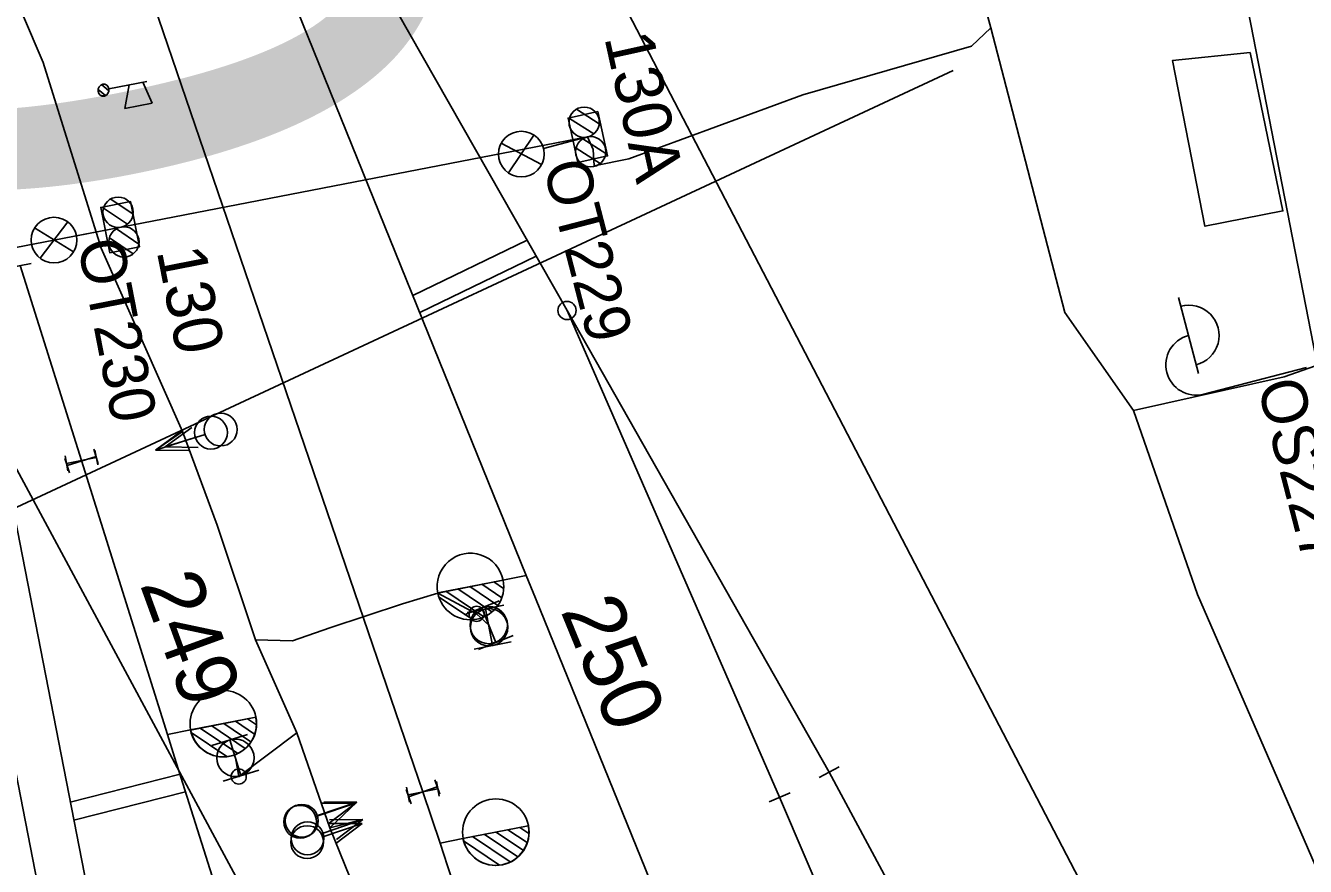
# Model space of a CAD drawing. Extents: x -545846 to -545044, y -1122650 to -1119108.
# Drawn here: x -545614.75 to -545572.52, y -1119663.02 to -1119635.26 of the extents above; entities that cross this region are included whole.
import ezdxf

# ---------------------------------------------------------------- set-up
doc = ezdxf.new("R2010")
doc.units = 0
for name, color, linetype in [('osvětlené plochy-hodnota-obrys', 7, 'Continuous'), ('Vrstva 1', 7, 'Continuous'), ('Vrstva 11 - Trakce', 7, 'Continuous'), ('Vrstva 12', 7, 'Continuous'), ('Vrstva 12 - Trakce zaklady', 7, 'Continuous'), ('Vrstva 2', 7, 'Continuous'), ('Vrstva 25', 7, 'Continuous'), ('Vrstva 26', 7, 'Continuous'), ('Vrstva 27', 7, 'Continuous'), ('Vrstva 28 - zabzar', 7, 'Continuous'), ('Vrstva 3', 7, 'Continuous'), ('Vrstva 3 - Lisy - Pocitaci body', 7, 'Continuous'), ('Vrstva 33', 7, 'Continuous'), ('Vrstva 35', 7, 'Continuous'), ('Vrstva 4 - Teren - stezky - prechody - plochy', 7, 'Continuous'), ('Vrstva 63', 7, 'Continuous'), ('Vrstva 7', 7, 'Continuous')]:
    doc.layers.add(name, color=color, linetype=linetype)

msp = doc.modelspace()

# ---------------------------------------------------------------- linework, layer by layer
at = {"layer": 'osvětlené plochy-hodnota-obrys'}
msp.add_line((-545562.16, -1119697.713), (-545631.883, -1119563.683), dxfattribs=at)
for points in [[(-545441.658, -1120319.908), (-545444.67, -1120302.28), (-545584.854, -1119581.025)], [(-545577.736, -1119667.874), (-545599.026, -1119679.685), (-545626.403, -1119628.801)]]:
    msp.add_lwpolyline(points, dxfattribs=at)
at = {"layer": 'Vrstva 1'}
for p, q in [((-545607.841, -1119629.659), (-545598.232, -1119653.414)), ((-545596.887, -1119644.663), (-545589.872, -1119660.732))]:
    msp.add_line(p, q, dxfattribs=at)
for points in [[(-545618.295, -1119613.58), (-545616.929, -1119617.292), (-545611.113, -1119632.817), (-545601.641, -1119660.552), (-545601.077, -1119662.243)], [(-545604.672, -1119630.951), (-545604.24, -1119631.719), (-545596.887, -1119644.663), (-545588.234, -1119659.903)], [(-545614.934, -1119643.182), (-545612.911, -1119649.615), (-545610.067, -1119658.662)], [(-545616.651, -1119643.635), (-545609.752, -1119678.959), (-545604.997, -1119703.439)], [(-545598.232, -1119653.414), (-545597.93, -1119654.159), (-545592.335, -1119667.955), (-545585.744, -1119684.209)], [(-545610.067, -1119658.662), (-545609.834, -1119659.409), (-545607.007, -1119668.348), (-545602.189, -1119683.602)], [(-545588.234, -1119659.903), (-545581.761, -1119671.962), (-545577.409, -1119681.094), (-545571.948, -1119694.17)], [(-545589.872, -1119660.732), (-545584.463, -1119673.383), (-545580.691, -1119682.438), (-545575.646, -1119695.886)], [(-545601.077, -1119662.243), (-545600.827, -1119662.999), (-545596.107, -1119677.118), (-545590.549, -1119693.752)]]:
    msp.add_lwpolyline(points, dxfattribs=at)
at = {"layer": 'Vrstva 11 - Trakce'}
for p, q in [((-545596.579, -1119638.02), (-545595.826, -1119638.5)), ((-545596.803, -1119638.322), (-545596.003, -1119638.832)), ((-545596.365, -1119638.999), (-545595.61, -1119639.48)), ((-545596.588, -1119639.302), (-545595.79, -1119639.81)), ((-545611.945, -1119640.986), (-545611.205, -1119641.483)), ((-545612.177, -1119641.282), (-545611.39, -1119641.811)), ((-545611.755, -1119641.969), (-545611.012, -1119642.469)), ((-545611.985, -1119642.267), (-545611.2, -1119642.794))]:
    msp.add_line(p, q, dxfattribs=at)
msp.add_lwpolyline([(-545596.214, -1119638.936), (-545611.603, -1119641.91), (-545639.182, -1119647.235)], dxfattribs=at)
for centre in [(-545596.322, -1119638.448), (-545596.106, -1119639.424), (-545611.699, -1119641.419), (-545611.507, -1119642.401)]:
    msp.add_circle(centre, 0.5, dxfattribs=at)
at = {"layer": 'Vrstva 12'}
msp.add_lwpolyline([(-545574.352, -1119636.15), (-545576.905, -1119636.409), (-545575.84, -1119641.883), (-545573.267, -1119641.376)], close=True, dxfattribs=at)
at = {"layer": 'Vrstva 12 - Trakce zaklady'}
for p, q in [((-545595.876, -1119638.097), (-545595.552, -1119639.561)), ((-545612.27, -1119641.262), (-545611.289, -1119641.07)), ((-545612.27, -1119641.262), (-545612.27, -1119641.262)), ((-545611.977, -1119642.757), (-545610.996, -1119642.565))]:
    msp.add_line(p, q, dxfattribs=at)
for points in [[(-545596.528, -1119639.777), (-545596.852, -1119638.313), (-545595.876, -1119638.097), (-545595.552, -1119639.561), (-545596.528, -1119639.777)], [(-545596.852, -1119638.313), (-545595.876, -1119638.097), (-545595.876, -1119638.097)], [(-545596.852, -1119638.313), (-545596.852, -1119638.313), (-545596.528, -1119639.777), (-545596.528, -1119639.777)], [(-545596.528, -1119639.777), (-545595.552, -1119639.561), (-545595.552, -1119639.561)], [(-545611.289, -1119641.07), (-545610.996, -1119642.565), (-545611.977, -1119642.757), (-545612.27, -1119641.262), (-545611.289, -1119641.07)], [(-545611.289, -1119641.07), (-545611.289, -1119641.07), (-545610.996, -1119642.565), (-545610.996, -1119642.565)], [(-545612.27, -1119641.262), (-545611.977, -1119642.757), (-545611.977, -1119642.757)]]:
    msp.add_lwpolyline(points, dxfattribs=at)
at = {"layer": 'Vrstva 2'}
for p, q in [((-545614.566, -1119643.11), (-545615.302, -1119643.254)), ((-545596.887, -1119644.663), (-545589.872, -1119660.732)), ((-545601.151, -1119653.986), (-545598.996, -1119653.566)), ((-545601.148, -1119653.992), (-545598.232, -1119653.414)), ((-545599.175, -1119654.401), (-545600.097, -1119653.78)), ((-545599.043, -1119654.147), (-545599.702, -1119653.703)), ((-545598.98, -1119653.845), (-545599.306, -1119653.626)), ((-545601.151, -1119653.986), (-545601.151, -1119653.986)), ((-545600.009, -1119654.87), (-545601.111, -1119654.128)), ((-545599.634, -1119654.779), (-545600.888, -1119653.934)), ((-545599.369, -1119654.614), (-545600.493, -1119653.857)), ((-545609.31, -1119658.512), (-545607.155, -1119658.093)), ((-545607.155, -1119658.093), (-545609.31, -1119658.513)), ((-545608.997, -1119658.451), (-545607.754, -1119659.289)), ((-545608.607, -1119658.375), (-545607.502, -1119659.12)), ((-545608.216, -1119658.3), (-545607.318, -1119658.905)), ((-545607.826, -1119658.224), (-545607.194, -1119658.649)), ((-545607.435, -1119658.147), (-545607.138, -1119658.347)), ((-545609.311, -1119658.512), (-545610.067, -1119658.662)), ((-545609.31, -1119658.513), (-545609.31, -1119658.512)), ((-545609.288, -1119658.594), (-545608.107, -1119659.39)), ((-545587.904, -1119659.726), (-545588.564, -1119660.08)), ((-545590.216, -1119660.88), (-545589.528, -1119660.584)), ((-545600.32, -1119662.093), (-545598.165, -1119661.674)), ((-545598.165, -1119661.674), (-545600.32, -1119662.094)), ((-545598.836, -1119661.805), (-545598.204, -1119662.23)), ((-545598.445, -1119661.728), (-545598.148, -1119661.928)), ((-545600.321, -1119662.093), (-545601.077, -1119662.243)), ((-545600.32, -1119662.094), (-545600.32, -1119662.093)), ((-545600.298, -1119662.175), (-545599.117, -1119662.971)), ((-545600.007, -1119662.032), (-545598.764, -1119662.87)), ((-545599.617, -1119661.956), (-545598.512, -1119662.701)), ((-545599.226, -1119661.881), (-545598.328, -1119662.486))]:
    msp.add_line(p, q, dxfattribs=at)
for points in [[(-545604.672, -1119630.951), (-545604.24, -1119631.719), (-545596.887, -1119644.663), (-545588.234, -1119659.903)], [(-545598.232, -1119653.414), (-545597.93, -1119654.159), (-545592.335, -1119667.955), (-545585.744, -1119684.209)], [(-545610.067, -1119658.662), (-545609.834, -1119659.409), (-545607.007, -1119668.348), (-545602.189, -1119683.602)], [(-545601.077, -1119662.243), (-545600.827, -1119662.999), (-545596.107, -1119677.118), (-545590.549, -1119693.752)]]:
    msp.add_lwpolyline(points, dxfattribs=at)
for centre, radius in [((-545596.887, -1119644.663), 0.3), ((-545608.226, -1119658.303), 1.097), ((-545599.236, -1119661.884), 1.097)]:
    msp.add_circle(centre, radius, dxfattribs=at)
for centre, radius, start, end in [((-545600.073, -1119653.774), 1.097, 10.9812, 191.4507), ((-545600.073, -1119653.776), 1.098, 191.0707, 11.0315), ((-545608.233, -1119658.303), 1.098, 191.0475, 11.0084), ((-545599.243, -1119661.884), 1.098, 191.0475, 11.0084)]:
    msp.add_arc(centre, radius, start, end, dxfattribs=at)
at = {"layer": 'Vrstva 25'}
for p, q in [((-545598.818, -1119640.125), (-545597.98, -1119638.872)), ((-545597.666, -1119639.313), (-545596.214, -1119638.936)), ((-545599.057, -1119639.139), (-545597.728, -1119639.85)), ((-545614.454, -1119641.937), (-545613.17, -1119642.729)), ((-545614.275, -1119642.936), (-545613.362, -1119641.737)), ((-545613.075, -1119642.197), (-545611.603, -1119641.91)), ((-545576.055, -1119646.748), (-545576.709, -1119644.232)), ((-545572.492, -1119646.546), (-545575.879, -1119647.426))]:
    msp.add_line(p, q, dxfattribs=at)
msp.add_lwpolyline([(-545611.603, -1119641.91), (-545639.182, -1119647.235)], dxfattribs=at)
for centre in [(-545598.396, -1119639.5), (-545613.816, -1119642.339)]:
    msp.add_circle(centre, 0.754, dxfattribs=at)
for centre, start, end in [((-545576.371, -1119645.487), 283.8627, 105.2679), ((-545576.131, -1119646.458), 104.5653, 284.5653)]:
    msp.add_arc(centre, 1, start, end, dxfattribs=at)
at = {"layer": 'Vrstva 26'}
for points in [[(-545578.197, -1119647.96), (-545580.459, -1119644.735), (-545582.903, -1119635.329), (-545585.075, -1119627.41), (-545588.377, -1119617.488), (-545589.973, -1119609.531), (-545593.406, -1119595.847), (-545595.043, -1119586.959), (-545596.508, -1119582.71), (-545595.465, -1119581.392), (-545593.58, -1119580.619)], [(-545582.903, -1119635.329), (-545583.54, -1119635.94), (-545589.11, -1119637.54), (-545594.85, -1119639.66), (-545595.99, -1119639.89), (-545596.03, -1119639.35), (-545596.214, -1119638.936)], [(-545557.858, -1119720.55), (-545560.745, -1119706.901), (-545565.918, -1119679.609), (-545568.797, -1119670.817), (-545576.09, -1119654.042), (-545578.197, -1119647.96), (-545573.229, -1119646.859), (-545572.008, -1119646.42)]]:
    msp.add_lwpolyline(points, dxfattribs=at)
at = {"layer": 'Vrstva 27'}
for p, q in [((-545599.878, -1119654.656), (-545599.862, -1119654.704)), ((-545607.728, -1119660.026), (-545607.712, -1119660.074))]:
    msp.add_line(p, q, dxfattribs=at)
for centre in [(-545599.87, -1119654.68), (-545607.72, -1119660.05)]:
    msp.add_circle(centre, 0.25, dxfattribs=at)
at = {"layer": 'Vrstva 28 - zabzar'}
msp.add_line((-545610.47, -1119649.27), (-545609.58, -1119648.66), dxfattribs=at)
for points in [[(-545602.41, -1119663.83), (-545602.8, -1119663.39), (-545603.89, -1119663.78), (-545604.71, -1119661.74), (-545605.8, -1119658.61), (-545607.17, -1119655.54), (-545608.43, -1119651.75), (-545609.58, -1119648.66), (-545612.26, -1119642.61), (-545614.17, -1119636.48), (-545616.81, -1119630.32), (-545617.94, -1119624.77), (-545618.68, -1119621.46), (-545618.67, -1119619.01), (-545619.98, -1119615.4), (-545621.7, -1119610.72), (-545623.18, -1119606.89), (-545623.86, -1119604.94), (-545624.45, -1119605.24)], [(-545607.17, -1119655.54), (-545605.95, -1119655.57), (-545604.71, -1119655.14), (-545602.32, -1119654.35), (-545601.15, -1119654), (-545599.87, -1119654.68), (-545599.47, -1119655.05)], [(-545607.83, -1119659.43), (-545607.72, -1119660.05), (-545605.8, -1119658.61)], [(-545603.82, -1119660.89), (-545604.71, -1119661.74), (-545603.63, -1119661.47)]]:
    msp.add_lwpolyline(points, dxfattribs=at)
at = {"layer": 'Vrstva 3'}
for p, q in [((-545610.148, -1119649.17), (-545609.264, -1119648.53)), ((-545610.148, -1119649.17), (-545608.832, -1119648.756)), ((-545613.45, -1119649.466), (-545613.354, -1119649.956)), ((-545612.42, -1119649.519), (-545613.402, -1119649.711)), ((-545612.468, -1119649.274), (-545612.372, -1119649.764)), ((-545610.148, -1119649.17), (-545609.057, -1119649.189)), ((-545598.972, -1119654.397), (-545600.182, -1119654.633)), ((-545599.577, -1119654.515), (-545599.341, -1119655.725)), ((-545598.736, -1119655.607), (-545599.946, -1119655.843)), ((-545602.084, -1119660.893), (-545602.18, -1119660.402)), ((-545602.132, -1119660.648), (-545601.15, -1119660.456)), ((-545601.102, -1119660.702), (-545601.198, -1119660.211)), ((-545603.872, -1119660.923), (-545605.178, -1119661.369)), ((-545603.872, -1119660.923), (-545604.963, -1119660.931)), ((-545603.872, -1119660.923), (-545604.74, -1119661.584)), ((-545603.643, -1119661.594), (-545604.949, -1119662.04)), ((-545603.643, -1119661.594), (-545604.734, -1119661.602)), ((-545603.643, -1119661.594), (-545604.511, -1119662.255))]:
    msp.add_line(p, q, dxfattribs=at)
for centre, radius in [((-545608.314, -1119648.595), 0.542), ((-545599.458, -1119655.122), 0.616), ((-545605.692, -1119661.542), 0.542), ((-545605.463, -1119662.213), 0.542)]:
    msp.add_circle(centre, radius, dxfattribs=at)
at = {"layer": 'Vrstva 3 - Lisy - Pocitaci body'}
for p, q in [((-545610.47, -1119649.27), (-545609.586, -1119648.63)), ((-545610.47, -1119649.27), (-545609.154, -1119648.856)), ((-545613.457, -1119649.545), (-545613.307, -1119650.021)), ((-545612.428, -1119649.483), (-545613.382, -1119649.783)), ((-545612.503, -1119649.245), (-545612.353, -1119649.721)), ((-545610.47, -1119649.27), (-545609.379, -1119649.289)), ((-545600.272, -1119654.71), (-545599.13, -1119654.248)), ((-545599.239, -1119655.621), (-545599.701, -1119654.479)), ((-545599.81, -1119655.852), (-545598.668, -1119655.39)), ((-545607.427, -1119658.658), (-545608.602, -1119659.027)), ((-545608.015, -1119658.842), (-545607.645, -1119660.018)), ((-545607.058, -1119659.833), (-545608.233, -1119660.202)), ((-545602.194, -1119660.479), (-545602.032, -1119660.952)), ((-545601.167, -1119660.392), (-545602.113, -1119660.716)), ((-545601.248, -1119660.156), (-545601.086, -1119660.629)), ((-545603.82, -1119660.89), (-545605.126, -1119661.336)), ((-545603.82, -1119660.89), (-545604.911, -1119660.898)), ((-545603.82, -1119660.89), (-545604.688, -1119661.551)), ((-545603.63, -1119661.47), (-545604.936, -1119661.916)), ((-545603.63, -1119661.47), (-545604.721, -1119661.478)), ((-545603.63, -1119661.47), (-545604.498, -1119662.131))]:
    msp.add_line(p, q, dxfattribs=at)
for centre, radius in [((-545608.636, -1119648.695), 0.542), ((-545599.471, -1119655.048), 0.616), ((-545607.829, -1119659.432), 0.616), ((-545605.64, -1119661.509), 0.542), ((-545605.45, -1119662.089), 0.542)]:
    msp.add_circle(centre, radius, dxfattribs=at)
at = {"layer": 'Vrstva 33'}
for p, q in [((-545612.252, -1119637.209), (-545612.004, -1119637.409)), ((-545610.751, -1119637.105), (-545612.003, -1119637.343)), ((-545611.473, -1119637.993), (-545611.333, -1119637.215)), ((-545610.885, -1119637.13), (-545610.576, -1119637.823)), ((-545612.36, -1119637.374), (-545612.117, -1119637.57)), ((-545610.576, -1119637.823), (-545611.473, -1119637.993))]:
    msp.add_line(p, q, dxfattribs=at)
for major_axis in [(-0.044, -0.195), (-0.044, -0.196)]:
    msp.add_ellipse((-545612.181, -1119637.388), major_axis=major_axis, ratio=0.897978, dxfattribs=at)
at = {"layer": 'Vrstva 35'}
msp.add_lwpolyline([(-545605.95, -1119655.57), (-545604.71, -1119655.14), (-545602.32, -1119654.35), (-545601.15, -1119654)], dxfattribs=at)
at = {"layer": 'Vrstva 4 - Teren - stezky - prechody - plochy'}
msp.add_lwpolyline([(-545624.215, -1119622.224), (-545623.342, -1119622.007), (-545620.608, -1119632.171), (-545618.464, -1119642.593), (-545609.99, -1119685.9), (-545599.422, -1119740.168), (-545590.883, -1119784.038), (-545582.301, -1119828.162), (-545571.506, -1119883.387), (-545561.049, -1119937.185), (-545548.968, -1119999.368), (-545536.73, -1120062.107), (-545526.255, -1120115.744), (-545515.983, -1120168.544), (-545503.995, -1120229.495), (-545494.446, -1120278.921), (-545489.088, -1120306.388), (-545486.967, -1120316.535), (-545487.846, -1120316.754)], dxfattribs=at)
at = {"layer": 'Vrstva 63'}
msp.add_line((-545584.143, -1119636.743), (-545668.751, -1119676.21), dxfattribs=at)
at = {"layer": 'Vrstva 7'}
for p, q in [((-545601.971, -1119644.17), (-545598.203, -1119642.347)), ((-545601.746, -1119644.727), (-545597.906, -1119642.87)), ((-545613.279, -1119660.9), (-545609.655, -1119659.976)), ((-545613.164, -1119661.49), (-545609.473, -1119660.549))]:
    msp.add_line(p, q, dxfattribs=at)

# ---------------------------------------------------------------- texts
at = {"layer": 'osvětlené plochy-hodnota-obrys'}
msp.add_text('10', height=22.7812, rotation=281.0956, dxfattribs=at).set_placement((-545628.764, -1119610.287))
at = {"layer": 'Vrstva 11 - Trakce'}
for s, rotation, p in [('130A', 282.4791, (-545595.662, -1119635.65)), ('130', 281.0887, (-545610.429, -1119642.699))]:
    msp.add_text(s, height=1.6, rotation=rotation, dxfattribs=at).set_placement(p)
at = {"layer": 'Vrstva 2'}
for s, rotation, p in [('249', 290.0286, (-545610.991, -1119653.703)), ('250', 292.2788, (-545597.115, -1119654.574))]:
    msp.add_text(s, height=2, rotation=rotation, dxfattribs=at).set_placement(p)
at = {"layer": 'Vrstva 25'}
for s, rotation, p in [('OT229', 284.5653, (-545597.689, -1119639.887)), ('OT230', 281.0268, (-545613.045, -1119642.435)), ('OS227', 284.5653, (-545574.124, -1119647.113))]:
    msp.add_text(s, height=1.5, rotation=rotation, dxfattribs=at).set_placement(p)

doc.saveas('drawing.dxf')
